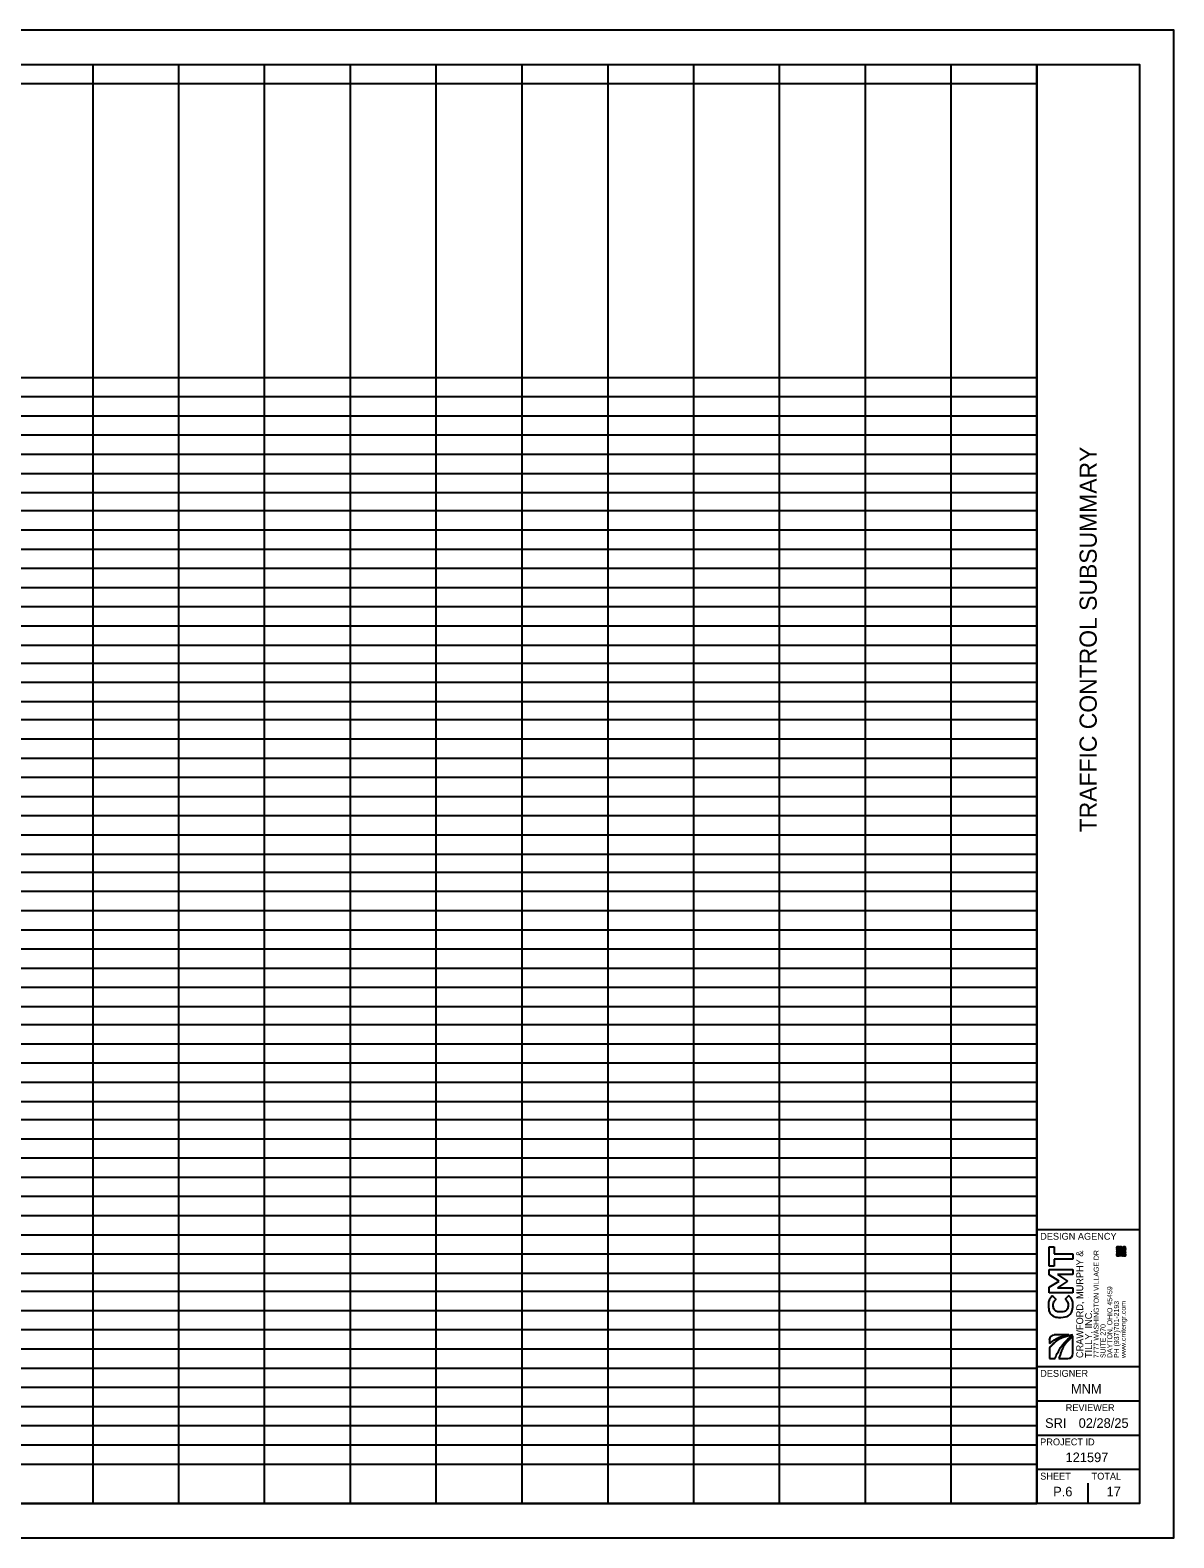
# Model space of a CAD drawing. Extents: x 0 to 34, y 0 to 22.
# Drawn here: x 17.31 to 34, y 0 to 22 of the extents above; entities that cross this region are included whole.
import ezdxf

# ---------------------------------------------------------------- set-up
doc = ezdxf.new("R2010")
doc.units = 0
for name, color, linetype in [('Common-Title block info', 7, 'Continuous'), ('Default', 7, 'Continuous'), ('LOGOS', 7, 'Continuous'), ('SH_Border', 7, 'Continuous'), ('SH_Cut_Line', 7, 'Continuous'), ('SH_Data', 7, 'Continuous')]:
    doc.layers.add(name, color=color, linetype=linetype)

msp = doc.modelspace()

# ---------------------------------------------------------------- linework, layer by layer
at = {"layer": 'Common-Title block info'}
for p, q in [((32.184, 2.889), (32.184, 2.838)), ((32.47, 2.96), (32.254, 2.96)), ((32.525, 2.96), (32.525, 2.96)), ((32.526, 2.688), (32.526, 2.941)), ((32.184, 2.773), (32.184, 2.618)), ((32.184, 2.618), (32.267, 2.618)), ((32.324, 2.618), (32.455, 2.618))]:
    msp.add_line(p, q, dxfattribs=at)
msp.add_lwpolyline([(32.526, 2.941), (32.526, 2.941)], dxfattribs=at)
for centre, start, end in [((32.254, 2.889), 90, 180), ((32.455, 2.688), 270, 360)]:
    msp.add_arc(centre, 0.0708, start, end, dxfattribs=at)
for points, degree in [([(32.525, 2.96), (32.393, 2.934), (32.272, 2.867), (32.184, 2.773)], 2), ([(32.184, 2.838), (32.266, 2.9), (32.365, 2.94), (32.47, 2.96)], 2), ([(32.267, 2.618), (32.267, 2.618), (32.267, 2.618), (32.267, 2.618), (32.323, 2.751), (32.412, 2.869), (32.525, 2.96)], 3), ([(32.526, 2.941), (32.434, 2.857), (32.367, 2.761), (32.324, 2.618)], 2)]:
    msp.add_open_spline(points, degree=degree, dxfattribs=at)
at = {"layer": 'Default'}
for p, q in [((10.711, 21.5), (21.982, 21.5)), ((18.225, 21.5), (18.225, 0.5)), ((19.477, 21.5), (19.477, 0.5)), ((20.729, 21.5), (20.729, 0.5)), ((21.982, 21.5), (32, 21.5)), ((21.982, 21.5), (21.982, 0.5)), ((23.234, 21.5), (23.234, 0.5)), ((24.486, 21.5), (24.486, 0.5)), ((25.739, 21.5), (25.739, 0.5)), ((26.991, 21.5), (26.991, 0.5)), ((28.243, 21.5), (28.243, 0.5)), ((29.495, 21.5), (29.495, 0.5)), ((30.748, 21.5), (30.748, 0.5)), ((32, 21.5), (32, 0.5)), ((10.711, 21.22), (32, 21.22)), ((10.711, 16.934), (32, 16.934)), ((1.5, 16.654), (32, 16.654)), ((1.5, 16.374), (32, 16.374)), ((1.5, 16.093), (32, 16.093)), ((1.5, 15.813), (32, 15.813)), ((1.5, 15.533), (32, 15.533)), ((1.5, 15.253), (32, 15.253)), ((1.5, 14.989), (32, 14.989)), ((1.5, 14.709), (32, 14.709)), ((1.5, 14.429), (32, 14.429)), ((1.5, 14.148), (32, 14.148)), ((1.5, 13.868), (32, 13.868)), ((1.5, 13.588), (32, 13.588)), ((1.5, 13.308), (32, 13.308)), ((1.5, 13.027), (32, 13.027)), ((1.5, 12.764), (32, 12.764)), ((1.5, 12.484), (32, 12.484)), ((1.5, 12.203), (32, 12.203)), ((1.5, 11.94), (32, 11.94)), ((1.5, 11.659), (32, 11.659)), ((1.5, 11.379), (32, 11.379)), ((1.5, 11.099), (32, 11.099)), ((1.5, 10.819), (32, 10.819)), ((1.5, 10.538), (32, 10.538)), ((1.5, 10.258), (32, 10.258)), ((1.5, 9.978), (32, 9.978)), ((1.5, 9.714), (32, 9.714)), ((1.5, 9.434), (32, 9.434)), ((1.5, 9.154), (32, 9.154)), ((1.5, 8.874), (32, 8.874)), ((1.5, 8.593), (32, 8.593)), ((1.5, 8.313), (32, 8.313)), ((1.5, 8.033), (32, 8.033)), ((1.5, 7.753), (32, 7.753)), ((1.5, 7.489), (32, 7.489)), ((1.5, 7.209), (32, 7.209)), ((1.5, 6.929), (32, 6.929)), ((1.5, 6.648), (32, 6.648)), ((1.5, 6.368), (32, 6.368)), ((1.5, 6.104), (32, 6.104)), ((1.5, 5.824), (32, 5.824)), ((1.5, 5.544), (32, 5.544)), ((1.5, 5.264), (32, 5.264)), ((1.5, 4.984), (32, 4.984)), ((1.5, 4.703), (32, 4.703)), ((1.5, 4.423), (32, 4.423)), ((1.5, 4.143), (32, 4.143)), ((1.5, 3.863), (32, 3.863)), ((1.5, 3.599), (32, 3.599)), ((1.5, 3.319), (32, 3.319)), ((1.5, 3.038), (32, 3.038)), ((1.5, 2.758), (32, 2.758)), ((1.5, 2.478), (32, 2.478)), ((1.5, 2.198), (32, 2.198)), ((1.5, 1.918), (32, 1.918)), ((1.5, 1.637), (32, 1.637)), ((1.5, 1.357), (32, 1.357)), ((1.5, 1.077), (32, 1.077)), ((1.5, 0.5), (32, 0.5))]:
    msp.add_line(p, q, dxfattribs=at)
at = {"layer": 'LOGOS'}
for p, q in [((32.182, 3.964), (32.182, 4.248)), ((32.182, 4.248), (32.252, 4.248)), ((32.252, 4.248), (32.252, 4.143)), ((32.252, 3.964), (32.182, 3.964)), ((32.252, 4.143), (32.525, 4.143)), ((32.252, 4.068), (32.252, 3.964)), ((32.525, 4.068), (32.252, 4.068)), ((32.525, 4.143), (32.525, 4.068)), ((32.182, 3.837), (32.182, 3.918)), ((32.182, 3.918), (32.525, 3.918)), ((32.327, 3.747), (32.182, 3.837)), ((32.182, 3.657), (32.327, 3.747)), ((32.525, 3.843), (32.301, 3.843)), ((32.301, 3.843), (32.448, 3.747)), ((32.448, 3.745), (32.303, 3.649)), ((32.448, 3.747), (32.448, 3.745)), ((32.525, 3.918), (32.525, 3.843)), ((32.182, 3.575), (32.182, 3.657)), ((32.525, 3.575), (32.182, 3.575)), ((32.303, 3.649), (32.525, 3.649)), ((32.525, 3.649), (32.525, 3.575))]:
    msp.add_line(p, q, dxfattribs=at)
for points in [[(33.284, 4.243), (33.279, 4.243), (33.279, 4.239), (33.275, 4.239), (33.275, 4.23), (33.265, 4.23), (33.265, 4.234), (33.261, 4.234), (33.261, 4.239), (33.252, 4.239), (33.252, 4.225), (33.256, 4.225), (33.256, 4.221), (33.247, 4.221), (33.247, 4.216), (33.252, 4.216), (33.252, 4.212), (33.238, 4.212), (33.238, 4.221), (33.234, 4.221), (33.234, 4.225), (33.238, 4.225), (33.238, 4.221), (33.247, 4.221), (33.247, 4.225), (33.243, 4.225), (33.243, 4.234), (33.229, 4.234), (33.229, 4.239), (33.225, 4.239), (33.225, 4.243), (33.229, 4.243), (33.229, 4.239), (33.234, 4.239), (33.234, 4.243), (33.238, 4.243), (33.238, 4.248), (33.216, 4.248), (33.216, 4.243), (33.22, 4.243), (33.22, 4.23), (33.229, 4.23), (33.229, 4.225), (33.216, 4.225), (33.216, 4.221), (33.225, 4.221), (33.225, 4.216), (33.234, 4.216), (33.234, 4.212), (33.229, 4.212), (33.229, 4.207), (33.225, 4.207), (33.225, 4.216), (33.22, 4.216), (33.22, 4.212), (33.216, 4.212), (33.216, 4.207), (33.22, 4.207), (33.22, 4.203), (33.211, 4.203), (33.211, 4.212), (33.207, 4.212), (33.207, 4.207), (33.198, 4.207), (33.198, 4.203), (33.193, 4.203), (33.193, 4.207), (33.198, 4.207), (33.198, 4.212), (33.189, 4.212), (33.189, 4.207), (33.184, 4.207), (33.184, 4.212), (33.175, 4.212), (33.175, 4.203), (33.17, 4.203), (33.17, 4.207), (33.166, 4.207), (33.166, 4.198), (33.179, 4.198), (33.179, 4.184), (33.184, 4.184), (33.184, 4.189), (33.189, 4.189), (33.189, 4.193), (33.184, 4.193), (33.184, 4.203), (33.189, 4.203), (33.189, 4.193), (33.193, 4.193), (33.193, 4.198), (33.198, 4.198), (33.198, 4.193), (33.193, 4.193), (33.193, 4.189), (33.202, 4.189), (33.202, 4.203), (33.207, 4.203), (33.207, 4.198), (33.211, 4.198), (33.211, 4.193), (33.216, 4.193), (33.216, 4.198), (33.234, 4.198), (33.234, 4.193), (33.238, 4.193), (33.238, 4.184), (33.234, 4.184), (33.234, 4.18), (33.252, 4.18), (33.252, 4.184), (33.261, 4.184), (33.261, 4.18), (33.252, 4.18), (33.252, 4.171), (33.256, 4.171), (33.256, 4.162), (33.261, 4.162), (33.261, 4.166), (33.265, 4.166), (33.265, 4.175), (33.27, 4.175), (33.27, 4.157), (33.279, 4.157), (33.279, 4.166), (33.275, 4.166), (33.275, 4.171), (33.279, 4.171), (33.279, 4.166), (33.284, 4.166), (33.284, 4.157), (33.279, 4.157), (33.279, 4.153), (33.288, 4.153), (33.288, 4.162), (33.297, 4.162), (33.297, 4.171), (33.293, 4.171), (33.293, 4.166), (33.288, 4.166), (33.288, 4.175), (33.279, 4.175), (33.279, 4.18), (33.284, 4.18), (33.284, 4.184), (33.297, 4.184), (33.297, 4.189), (33.293, 4.189), (33.293, 4.193), (33.297, 4.193), (33.297, 4.212), (33.284, 4.212), (33.284, 4.207), (33.293, 4.207), (33.293, 4.203), (33.284, 4.203), (33.284, 4.198), (33.279, 4.198), (33.279, 4.193), (33.275, 4.193), (33.275, 4.198), (33.27, 4.198), (33.27, 4.207), (33.279, 4.207), (33.279, 4.225), (33.284, 4.225)], [(33.198, 4.248), (33.166, 4.248), (33.166, 4.216), (33.198, 4.216)], [(33.179, 4.184), (33.175, 4.184), (33.175, 4.193), (33.166, 4.193), (33.166, 4.171), (33.17, 4.171), (33.17, 4.166), (33.175, 4.166), (33.175, 4.162), (33.17, 4.162), (33.17, 4.157), (33.179, 4.157), (33.179, 4.162), (33.184, 4.162), (33.184, 4.18), (33.179, 4.18)], [(33.193, 4.243), (33.193, 4.221), (33.17, 4.221), (33.17, 4.243)], [(33.189, 4.239), (33.175, 4.239), (33.175, 4.225), (33.189, 4.225)], [(33.202, 4.189), (33.202, 4.184), (33.193, 4.184), (33.193, 4.18), (33.198, 4.18), (33.198, 4.175), (33.202, 4.175), (33.202, 4.171), (33.198, 4.171), (33.198, 4.166), (33.207, 4.166), (33.207, 4.175), (33.211, 4.175), (33.211, 4.18), (33.207, 4.18), (33.207, 4.189)], [(33.216, 4.243), (33.211, 4.243), (33.211, 4.239), (33.207, 4.239), (33.207, 4.23), (33.202, 4.23), (33.202, 4.225), (33.207, 4.225), (33.207, 4.221), (33.202, 4.221), (33.202, 4.212), (33.207, 4.212), (33.207, 4.216), (33.216, 4.216), (33.216, 4.221), (33.211, 4.221), (33.211, 4.225), (33.216, 4.225)], [(33.211, 4.243), (33.211, 4.248), (33.207, 4.248), (33.207, 4.243)], [(33.211, 4.18), (33.216, 4.18), (33.216, 4.175), (33.22, 4.175), (33.22, 4.157), (33.229, 4.157), (33.229, 4.153), (33.234, 4.153), (33.234, 4.162), (33.225, 4.162), (33.225, 4.166), (33.234, 4.166), (33.234, 4.171), (33.229, 4.171), (33.229, 4.175), (33.225, 4.175), (33.225, 4.18), (33.22, 4.18), (33.22, 4.189), (33.211, 4.189)], [(33.225, 4.189), (33.225, 4.193), (33.22, 4.193), (33.22, 4.189)], [(33.234, 4.184), (33.234, 4.189), (33.225, 4.189), (33.225, 4.18), (33.229, 4.18), (33.229, 4.184)], [(33.265, 4.198), (33.265, 4.193), (33.27, 4.193), (33.27, 4.189), (33.279, 4.189), (33.279, 4.184), (33.275, 4.184), (33.275, 4.18), (33.27, 4.18), (33.27, 4.184), (33.265, 4.184), (33.265, 4.189), (33.261, 4.189), (33.261, 4.193), (33.256, 4.193), (33.256, 4.198), (33.252, 4.198), (33.252, 4.193), (33.247, 4.193), (33.247, 4.189), (33.243, 4.189), (33.243, 4.198), (33.238, 4.198), (33.238, 4.207), (33.252, 4.207), (33.252, 4.203), (33.261, 4.203), (33.261, 4.198)], [(33.252, 4.198), (33.252, 4.203), (33.247, 4.203), (33.247, 4.198)], [(33.265, 4.234), (33.27, 4.234), (33.27, 4.243), (33.265, 4.243), (33.265, 4.248), (33.261, 4.248), (33.261, 4.239), (33.265, 4.239)], [(33.275, 4.225), (33.275, 4.212), (33.261, 4.212), (33.261, 4.225)], [(33.27, 4.221), (33.265, 4.221), (33.265, 4.216), (33.27, 4.216)], [(33.279, 4.243), (33.279, 4.248), (33.275, 4.248), (33.275, 4.243)], [(33.279, 4.203), (33.275, 4.203), (33.275, 4.198), (33.279, 4.198)], [(33.284, 4.207), (33.279, 4.207), (33.279, 4.203), (33.284, 4.203)], [(33.288, 4.243), (33.288, 4.248), (33.284, 4.248), (33.284, 4.243)], [(33.284, 4.225), (33.284, 4.221), (33.288, 4.221), (33.288, 4.225)], [(33.297, 4.239), (33.297, 4.243), (33.288, 4.243), (33.288, 4.239)], [(33.293, 4.225), (33.293, 4.234), (33.288, 4.234), (33.288, 4.225)], [(33.288, 4.221), (33.288, 4.216), (33.297, 4.216), (33.297, 4.225), (33.293, 4.225), (33.293, 4.221)], [(33.198, 4.148), (33.166, 4.148), (33.166, 4.117), (33.198, 4.117)], [(33.175, 4.18), (33.175, 4.175), (33.17, 4.175), (33.17, 4.18)], [(33.193, 4.144), (33.193, 4.121), (33.17, 4.121), (33.17, 4.144)], [(33.189, 4.126), (33.189, 4.139), (33.175, 4.139), (33.175, 4.126)], [(33.189, 4.153), (33.189, 4.157), (33.184, 4.157), (33.184, 4.153)], [(33.193, 4.18), (33.189, 4.18), (33.189, 4.175), (33.193, 4.175)], [(33.193, 4.175), (33.193, 4.171), (33.198, 4.171), (33.198, 4.175)], [(33.207, 4.166), (33.207, 4.162), (33.202, 4.162), (33.202, 4.157), (33.193, 4.157), (33.193, 4.153), (33.202, 4.153), (33.202, 4.144), (33.207, 4.144), (33.207, 4.157), (33.211, 4.157), (33.211, 4.162), (33.216, 4.162), (33.216, 4.166)], [(33.198, 4.166), (33.193, 4.166), (33.193, 4.162), (33.198, 4.162)], [(33.211, 4.135), (33.202, 4.135), (33.202, 4.126), (33.211, 4.126)], [(33.229, 4.153), (33.22, 4.153), (33.22, 4.139), (33.216, 4.139), (33.216, 4.148), (33.211, 4.148), (33.211, 4.135), (33.22, 4.135), (33.22, 4.126), (33.225, 4.126), (33.225, 4.13), (33.238, 4.13), (33.238, 4.135), (33.243, 4.135), (33.243, 4.13), (33.252, 4.13), (33.252, 4.126), (33.256, 4.126), (33.256, 4.121), (33.261, 4.121), (33.261, 4.13), (33.256, 4.13), (33.256, 4.139), (33.252, 4.139), (33.252, 4.148), (33.256, 4.148), (33.256, 4.144), (33.261, 4.144), (33.261, 4.153), (33.27, 4.153), (33.27, 4.157), (33.256, 4.157), (33.256, 4.153), (33.252, 4.153), (33.252, 4.157), (33.247, 4.157), (33.247, 4.153), (33.243, 4.153), (33.243, 4.157), (33.238, 4.157), (33.238, 4.153), (33.234, 4.153), (33.234, 4.148), (33.238, 4.148), (33.238, 4.144), (33.243, 4.144), (33.243, 4.148), (33.247, 4.148), (33.247, 4.139), (33.234, 4.139), (33.234, 4.135), (33.225, 4.135), (33.225, 4.139), (33.234, 4.139), (33.234, 4.148), (33.229, 4.148), (33.229, 4.144), (33.225, 4.144), (33.225, 4.148), (33.229, 4.148)], [(33.211, 4.126), (33.211, 4.117), (33.216, 4.117), (33.216, 4.126)], [(33.234, 4.18), (33.229, 4.18), (33.229, 4.175), (33.234, 4.175)], [(33.234, 4.121), (33.234, 4.126), (33.229, 4.126), (33.229, 4.121)], [(33.234, 4.171), (33.243, 4.171), (33.243, 4.166), (33.252, 4.166), (33.252, 4.171), (33.247, 4.171), (33.247, 4.175), (33.234, 4.175)], [(33.238, 4.121), (33.234, 4.121), (33.234, 4.117), (33.238, 4.117)], [(33.243, 4.166), (33.238, 4.166), (33.238, 4.162), (33.243, 4.162)], [(33.238, 4.13), (33.238, 4.121), (33.243, 4.121), (33.243, 4.13)], [(33.252, 4.117), (33.252, 4.121), (33.247, 4.121), (33.247, 4.117)], [(33.297, 4.148), (33.265, 4.148), (33.265, 4.117), (33.297, 4.117)], [(33.293, 4.144), (33.293, 4.121), (33.27, 4.121), (33.27, 4.144)], [(33.288, 4.139), (33.275, 4.139), (33.275, 4.126), (33.288, 4.126)], [(33.288, 4.175), (33.297, 4.175), (33.297, 4.18), (33.288, 4.18)]]:
    msp.add_lwpolyline(points, close=True, dxfattribs=at)
msp.add_open_spline([(32.35, 3.217), (32.35, 3.217), (32.349, 3.217), (32.349, 3.217), (32.251, 3.217), (32.172, 3.29), (32.172, 3.396), (32.172, 3.46), (32.193, 3.499), (32.224, 3.531), (32.224, 3.531), (32.28, 3.483), (32.28, 3.483), (32.256, 3.456), (32.241, 3.43), (32.241, 3.395), (32.241, 3.337), (32.289, 3.296), (32.348, 3.296), (32.348, 3.296), (32.349, 3.296), (32.349, 3.296), (32.407, 3.296), (32.456, 3.337), (32.456, 3.395), (32.456, 3.434), (32.441, 3.458), (32.416, 3.485), (32.416, 3.485), (32.465, 3.533), (32.465, 3.533), (32.502, 3.498), (32.526, 3.459), (32.526, 3.393), (32.526, 3.292), (32.448, 3.217), (32.35, 3.217)], degree=3, dxfattribs=at)
at = {"layer": 'SH_Border'}
for p, q in [((32, 0.5), (32, 21.5)), ((32, 4.5), (33.5, 4.5)), ((32, 2.5), (33.5, 2.5)), ((32, 2), (33.5, 2)), ((32, 1.5), (33.5, 1.5)), ((32, 1), (33.5, 1))]:
    msp.add_line(p, q, dxfattribs=at)
msp.add_lwpolyline([(1.5, 21.5), (33.5, 21.5), (33.5, 0.5), (1.5, 0.5)], close=True, dxfattribs=at)
at = {"layer": 'SH_Cut_Line'}
msp.add_lwpolyline([(0, 0), (34, 0), (34, 22), (0, 22)], close=True, dxfattribs=at)
at = {"layer": 'SH_Data'}
for p, q in [((32.75, 3.5), (32.75, 3.5)), ((32.375, 0.675), (32.375, 0.675)), ((32.75, 0.5), (32.75, 0.8))]:
    msp.add_line(p, q, dxfattribs=at)

# ---------------------------------------------------------------- texts
at = {"layer": 'LOGOS'}
for s, height, p in [('CRAWFORD, MURPHY &', 0.1, (32.677, 2.624)), ('7777 WASHINGTON VILLAGE DR', 0.07331, (32.904, 2.624)), ('DAYTON, OHIO 45459', 0.07331, (33.102, 2.624)), ('TILLY, INC.', 0.1, (32.806, 2.624)), ('PH (937)701-2193', 0.07331, (33.2, 2.624)), ('www.cmtengr.com', 0.07331, (33.299, 2.624)), ('SUITE 270', 0.0733, (33.003, 2.624))]:
    msp.add_text(s, height=height, rotation=90, dxfattribs=at).set_placement(p)
at = {"layer": 'SH_Data'}
msp.add_text('TRAFFIC CONTROL SUBSUMMARY', height=0.25, rotation=90, dxfattribs=at).set_placement((32.875, 10.295))
for s, height, p in [('DESIGN AGENCY', 0.1, (32.05, 4.35)), ('DESIGNER', 0.1, (32.05, 2.35)), ('MNM', 0.14, (32.499, 2.105)), ('REVIEWER', 0.1, (32.422, 1.85)), ('SRI', 0.14, (32.121, 1.605)), ('02/28/25', 0.14, (32.611, 1.605)), ('PROJECT ID', 0.1, (32.05, 1.35)), ('121597', 0.14, (32.42, 1.105)), ('SHEET', 0.1, (32.05, 0.85)), ('TOTAL', 0.1, (32.8, 0.85)), ('P.6', 0.14, (32.239, 0.605)), ('17', 0.14, (33.018, 0.605))]:
    msp.add_text(s, height=height, dxfattribs=at).set_placement(p)

doc.saveas('drawing.dxf')
